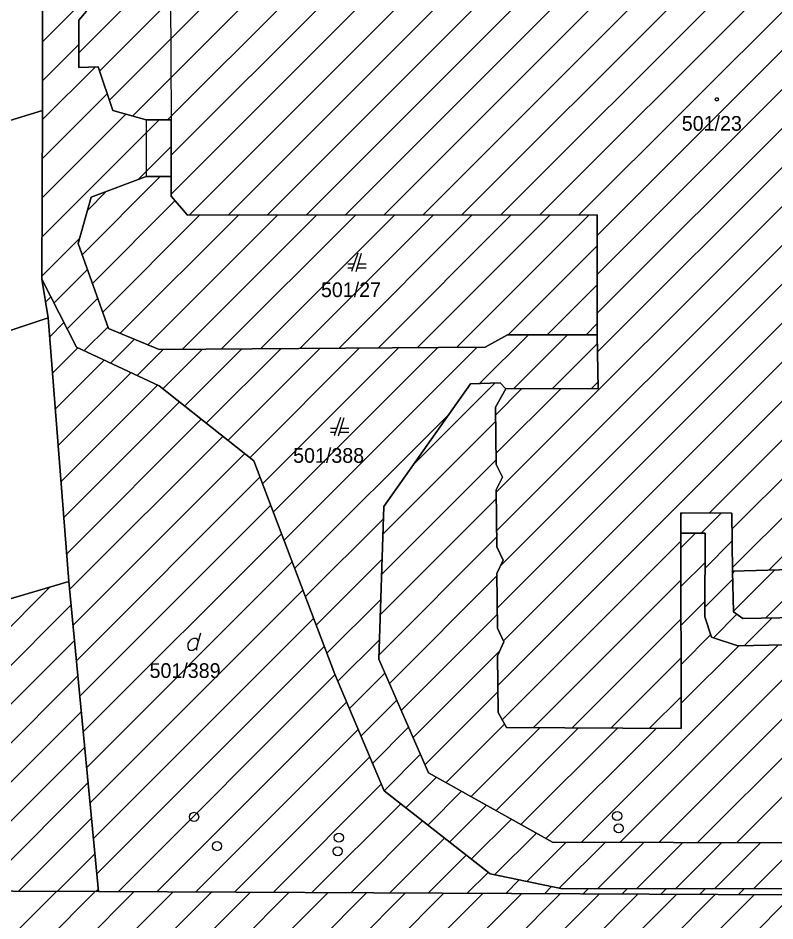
# Model space of a CAD drawing. Extents: x -264309 to -263505, y -1242443 to -1241763.
# Drawn here: x -264079.6 to -263997.1, y -1242199.4 to -1242101 of the extents above; entities that cross this region are included whole.
import ezdxf

# ---------------------------------------------------------------- set-up
doc = ezdxf.new("R2010")
doc.units = 0
for name, color, linetype in [('KFA_SO_40-3_SACHTY_POKLOPY', 7, 'Continuous'), ('KN_2019_08_16_KLADPAR', 7, 'Continuous'), ('KN_2019_08_16_ZAPPAR', 7, 'Continuous'), ('SRAFY_PARCELY', 7, 'Continuous')]:
    doc.layers.add(name, color=color, linetype=linetype)

msp = doc.modelspace()

# ---------------------------------------------------------------- linework, layer by layer
at = {"layer": 'KFA_SO_40-3_SACHTY_POKLOPY'}
for centre in [(-264014.309, -1242187.956), (-264060.398, -1242188.048), (-264014.146, -1242189.299), (-264044.631, -1242190.302), (-264057.903, -1242191.227), (-264044.758, -1242191.792)]:
    msp.add_circle(centre, 0.5, dxfattribs=at)
at = {"layer": 'KN_2019_08_16_KLADPAR'}
for p, q in [((-264042.56, -1242126.66), (-264043.26, -1242128.66)), ((-264042.76, -1242128.66), (-264042.16, -1242126.66)), ((-264042.98, -1242127.86), (-264043.66, -1242127.86)), ((-264043.66, -1242128.26), (-264043.12, -1242128.26)), ((-264042.64, -1242128.26), (-264041.66, -1242128.26)), ((-264041.66, -1242127.86), (-264042.52, -1242127.86)), ((-264044.45, -1242144.55), (-264045.15, -1242146.55)), ((-264044.65, -1242146.55), (-264044.05, -1242144.55)), ((-264044.87, -1242145.75), (-264045.55, -1242145.75)), ((-264045.55, -1242146.15), (-264045.01, -1242146.15)), ((-264044.53, -1242146.15), (-264043.55, -1242146.15)), ((-264043.55, -1242145.75), (-264044.41, -1242145.75)), ((-264059.92, -1242168.89), (-264059.65, -1242167.99))]:
    msp.add_line(p, q, dxfattribs=at)
for points in [[(-264246.81, -1242153.57), (-264207.96, -1242133.21), (-264176.83, -1242121.28), (-264120.91, -1242102.78), (-264081.08, -1242089.93), (-264076.9, -1242098.2), (-264076.93, -1242111.1), (-264102.41, -1242118.92), (-264128.45, -1242126.51), (-264158.28, -1242134.19), (-264188.56, -1242145.27), (-264215.11, -1242156.51), (-264222.8, -1242159.81), (-264237.43, -1242168.42)], [(-264003.37, -1242109.74), (-264003.28, -1242109.89), (-264003.37, -1242110.04), (-264003.55, -1242110.04), (-264003.64, -1242109.89), (-264003.55, -1242109.74)], [(-264076.93, -1242111.1), (-264076.98, -1242129.46), (-264076.3, -1242133.7), (-264095.55, -1242140.08), (-264157.05, -1242153.68), (-264195.05, -1242168.92), (-264211.96, -1242175.6), (-264215.03, -1242177.17), (-264227.71, -1242183.68), (-264237.43, -1242168.42), (-264222.8, -1242159.81), (-264215.11, -1242156.51), (-264188.56, -1242145.27), (-264158.28, -1242134.19), (-264128.45, -1242126.51), (-264102.41, -1242118.92)], [(-264016.47, -1242135.53), (-264026.27, -1242135.54), (-264028.68, -1242136.88), (-264064.2, -1242137.12), (-264069.71, -1242134.85), (-264073.04, -1242125.6), (-264071.61, -1242120.55), (-264065.61, -1242118.31), (-264062.88, -1242118.3), (-264062.88, -1242120.44), (-264061.11, -1242122.5), (-264016.48, -1242122.48)], [(-263988.88, -1242124.89), (-263983.88, -1242124.73), (-263977.77, -1242124.63), (-263973.88, -1242126.53), (-263972.33, -1242129.65), (-263972.09, -1242163.43), (-263972.93, -1242164.99), (-263974.51, -1242165.96), (-264000.63, -1242166.44), (-264001.62, -1242165.72), (-264001.73, -1242161.29), (-263988.91, -1242160.93)], [(-264070.8, -1242196.19), (-264074.04, -1242162.41), (-264076.3, -1242133.7), (-264076.98, -1242129.46), (-264073.21, -1242136.9), (-264064.2, -1242141.11), (-264053.9, -1242149.28), (-264045.08, -1242172.51), (-264039.7, -1242185.21), (-264028.16, -1242194.26), (-264020.26, -1242195.89), (-263967.07, -1242195.86), (-263959.05, -1242193.86), (-263950.83, -1242187.66), (-263949.38, -1242187.85), (-263949.41, -1242196.68), (-263950.84, -1242196.76)], [(-264195.05, -1242168.92), (-264157.05, -1242153.68), (-264095.55, -1242140.08), (-264076.3, -1242133.7), (-264074.04, -1242162.41), (-264177.6, -1242192.97)], [(-264212.29, -1242180.92), (-264215.03, -1242177.17), (-264211.96, -1242175.6), (-264195.05, -1242168.92), (-264177.6, -1242192.97), (-264074.04, -1242162.41), (-264070.8, -1242196.19), (-264098.84, -1242196.05), (-264099.36, -1242306.05), (-264115.27, -1242315.84), (-264137.78, -1242284.52)], [(-263950.84, -1242196.76), (-263951.29, -1242290.6), (-263951.37, -1242306.76), (-264045.86, -1242306.31), (-264099.36, -1242306.05), (-264098.84, -1242196.05), (-264070.8, -1242196.19)]]:
    msp.add_lwpolyline(points, close=True, dxfattribs=at)
for points in [[(-263967.07, -1242195.86), (-264020.26, -1242195.89), (-264028.16, -1242194.26), (-264039.7, -1242185.21), (-264045.08, -1242172.51), (-264053.9, -1242149.28), (-264064.2, -1242141.11), (-264073.21, -1242136.9), (-264076.98, -1242129.46), (-264076.93, -1242111.1), (-264076.9, -1242098.2)], [(-264072.11, -1242100.28), (-264072.96, -1242101.25), (-264072.96, -1242106.41), (-264070.85, -1242106.36), (-264069.25, -1242111.12), (-264065.62, -1242112.13), (-264062.89, -1242112.12), (-264062.88, -1242118.3), (-264065.61, -1242118.31), (-264071.61, -1242120.55), (-264073.04, -1242125.6), (-264069.71, -1242134.85), (-264064.2, -1242137.12), (-264028.68, -1242136.88), (-264026.27, -1242135.54), (-264016.47, -1242135.53), (-264016.38, -1242141.37), (-264026.42, -1242141.41), (-264027.07, -1242140.78), (-264030.29, -1242140.89), (-264039.73, -1242154.25), (-264040.29, -1242170.87), (-264034.85, -1242183.24), (-264021.34, -1242190.81), (-263968.63, -1242190.95)], [(-263988.91, -1242160.93), (-264001.73, -1242161.29), (-264001.8, -1242154.96), (-264007.36, -1242154.93), (-264007.37, -1242157.14), (-264007.34, -1242178.42), (-264026.37, -1242178.31), (-264027.29, -1242176.68), (-264027.34, -1242170.52), (-264026.65, -1242168.99), (-264027.36, -1242167.48), (-264027.41, -1242161.52), (-264026.72, -1242160.07), (-264027.43, -1242158.63), (-264027.48, -1242152.43), (-264026.79, -1242151.05), (-264027.5, -1242149.68), (-264027.55, -1242143.43), (-264026.42, -1242141.41), (-264016.38, -1242141.37), (-264016.47, -1242135.53), (-264016.48, -1242122.48), (-264061.11, -1242122.5), (-264062.88, -1242120.44), (-264062.88, -1242118.3), (-264062.89, -1242112.12), (-264065.62, -1242112.13), (-264069.25, -1242111.12), (-264070.85, -1242106.36), (-264072.96, -1242106.41), (-264072.96, -1242101.25), (-264072.11, -1242100.28)], [(-263968.63, -1242190.95), (-264021.34, -1242190.81), (-264034.85, -1242183.24), (-264040.29, -1242170.87), (-264039.73, -1242154.25), (-264030.29, -1242140.89), (-264027.07, -1242140.78), (-264026.42, -1242141.41), (-264027.55, -1242143.43), (-264027.5, -1242149.68), (-264026.79, -1242151.05), (-264027.48, -1242152.43), (-264027.43, -1242158.63), (-264026.72, -1242160.07), (-264027.41, -1242161.52), (-264027.36, -1242167.48), (-264026.65, -1242168.99), (-264027.34, -1242170.52), (-264027.29, -1242176.68), (-264026.37, -1242178.31), (-264007.34, -1242178.42), (-264007.37, -1242157.14), (-264004.73, -1242157.15), (-264004.75, -1242166.25), (-264004.02, -1242168.46), (-264001.16, -1242169.4), (-263955.56, -1242168.43)], [(-263955.56, -1242168.43), (-264001.16, -1242169.4), (-264004.02, -1242168.46), (-264004.75, -1242166.25), (-264004.73, -1242157.15), (-264007.37, -1242157.14), (-264007.36, -1242154.93), (-264001.8, -1242154.96), (-264001.73, -1242161.29), (-264001.62, -1242165.72), (-264000.63, -1242166.44), (-263974.51, -1242165.96)], [(-264060.1, -1242169.88), (-264060.1, -1242169.61), (-264059.92, -1242168.89), (-264060.01, -1242168.71), (-264060.19, -1242168.62), (-264060.46, -1242168.62), (-264060.73, -1242168.71), (-264060.91, -1242168.89), (-264061.09, -1242169.16), (-264061.09, -1242169.52), (-264061, -1242169.79), (-264060.82, -1242169.88), (-264060.55, -1242169.88), (-264060.37, -1242169.79), (-264060.1, -1242169.61)]]:
    msp.add_lwpolyline(points, dxfattribs=at)
at = {"layer": 'KN_2019_08_16_ZAPPAR'}
for p, q in [((-264063.02, -1242088.27), (-264062.89, -1242112.12)), ((-264065.62, -1242112.13), (-264065.61, -1242118.31))]:
    msp.add_line(p, q, dxfattribs=at)
at = {"layer": 'SRAFY_PARCELY'}
for p, q in [((-264072.96, -1242104.826), (-264045.841, -1242077.707)), ((-264070.699, -1242106.808), (-264041.592, -1242077.7)), ((-264069.632, -1242109.983), (-264037.342, -1242077.694)), ((-264067.119, -1242111.713), (-264033.093, -1242077.687)), ((-264063.285, -1242112.121), (-264028.844, -1242077.681)), ((-264062.884, -1242115.963), (-264024.595, -1242077.674)), ((-264062.88, -1242120.202), (-264020.346, -1242077.668)), ((-264060.935, -1242122.5), (-264016.097, -1242077.661)), ((-264056.691, -1242122.498), (-264011.848, -1242077.655)), ((-264052.446, -1242122.496), (-264007.599, -1242077.649)), ((-264048.202, -1242122.494), (-264003.35, -1242077.642)), ((-264043.957, -1242122.492), (-264001.663, -1242080.198)), ((-264039.713, -1242122.49), (-263997.265, -1242080.043)), ((-264035.468, -1242122.489), (-263993.026, -1242080.046)), ((-264031.224, -1242122.487), (-263988.846, -1242080.109)), ((-264026.979, -1242122.485), (-263984.667, -1242080.173)), ((-264022.735, -1242122.483), (-263981.762, -1242081.51)), ((-264018.49, -1242122.481), (-263977.519, -1242081.51)), ((-264016.478, -1242124.712), (-263975.759, -1242083.993)), ((-264016.475, -1242128.951), (-263975.725, -1242088.201)), ((-264016.472, -1242133.191), (-263975.69, -1242092.409)), ((-264016.441, -1242137.403), (-263972.66, -1242093.621)), ((-264027.478, -1242152.682), (-263970.237, -1242095.441)), ((-264076.913, -1242103.615), (-264072.792, -1242099.494)), ((-264027.444, -1242156.891), (-263970.23, -1242099.677)), ((-264076.922, -1242107.867), (-264072.96, -1242103.905)), ((-264076.933, -1242112.12), (-264071.18, -1242106.368)), ((-264076.944, -1242116.374), (-264069.864, -1242109.294)), ((-264027.028, -1242160.717), (-263975.58, -1242109.269)), ((-264076.956, -1242120.629), (-264067.84, -1242111.512)), ((-264076.968, -1242124.883), (-264064.21, -1242112.125)), ((-264066.475, -1242118.633), (-264062.885, -1242115.043)), ((-264072.603, -1242126.815), (-264064.092, -1242118.304)), ((-264072.017, -1242121.987), (-264069.967, -1242119.936)), ((-264071.48, -1242129.935), (-264062.466, -1242120.921)), ((-264070.356, -1242133.054), (-264059.802, -1242122.499)), ((-264068.435, -1242135.375), (-264055.557, -1242122.498)), ((-264065.43, -1242136.613), (-264051.313, -1242122.496)), ((-264061.677, -1242137.103), (-264047.068, -1242122.494)), ((-264057.406, -1242137.074), (-264042.823, -1242122.492)), ((-264053.134, -1242137.045), (-264038.579, -1242122.49)), ((-264048.863, -1242137.016), (-264034.334, -1242122.488)), ((-264044.591, -1242136.988), (-264030.09, -1242122.486)), ((-264040.32, -1242136.959), (-264025.845, -1242122.484)), ((-264036.048, -1242136.93), (-264021.601, -1242122.482)), ((-264031.777, -1242136.901), (-264017.356, -1242122.48)), ((-264076.979, -1242129.137), (-264072.881, -1242125.039)), ((-264026.173, -1242135.54), (-264016.477, -1242125.844)), ((-264027.378, -1242165.31), (-263988.882, -1242126.814)), ((-264075.661, -1242132.062), (-264072.023, -1242128.424)), ((-264021.926, -1242135.536), (-264016.474, -1242130.084)), ((-264076.577, -1242131.975), (-264075.999, -1242131.397)), ((-264026.703, -1242168.877), (-263988.885, -1242131.06)), ((-264074.235, -1242134.878), (-264070.9, -1242131.544)), ((-264076.136, -1242135.777), (-264074.572, -1242134.213)), ((-264017.679, -1242135.531), (-264016.471, -1242134.323)), ((-264072.395, -1242137.281), (-264069.777, -1242134.663)), ((-264027.314, -1242173.731), (-263988.889, -1242135.306)), ((-264069.503, -1242138.632), (-264066.885, -1242136.014)), ((-264029.301, -1242140.856), (-264023.983, -1242135.538)), ((-264025.609, -1242141.407), (-264019.736, -1242135.533)), ((-264075.827, -1242139.711), (-264073.078, -1242136.962)), ((-264066.612, -1242139.983), (-264063.746, -1242137.117)), ((-264063.808, -1242141.421), (-264059.474, -1242137.088)), ((-264061.442, -1242143.298), (-264055.203, -1242137.059)), ((-264059.076, -1242145.175), (-264050.931, -1242137.03)), ((-264056.71, -1242147.051), (-264046.66, -1242137.001)), ((-264054.344, -1242148.928), (-264042.388, -1242136.973)), ((-264052.951, -1242151.778), (-264038.117, -1242136.944)), ((-264051.784, -1242154.853), (-264033.845, -1242136.915)), ((-264050.616, -1242157.929), (-264029.574, -1242136.886)), ((-264021.35, -1242141.39), (-264016.455, -1242136.495)), ((-264075.517, -1242143.644), (-264070.186, -1242138.313)), ((-264075.208, -1242147.577), (-264067.295, -1242139.664)), ((-264004.287, -1242154.947), (-263988.892, -1242139.552)), ((-264074.898, -1242151.51), (-264064.403, -1242141.015)), ((-264036.5, -1242149.678), (-264027.62, -1242140.799)), ((-264017.09, -1242141.373), (-264016.391, -1242140.674)), ((-264027.543, -1242144.262), (-264024.684, -1242141.403)), ((-264027.51, -1242148.471), (-264020.425, -1242141.386)), ((-264074.588, -1242155.443), (-264062, -1242142.855)), ((-264049.449, -1242161.004), (-264032.589, -1242144.144)), ((-264001.781, -1242156.683), (-263988.896, -1242143.798)), ((-264074.279, -1242159.376), (-264059.635, -1242144.731)), ((-264039.831, -1242157.252), (-264027.538, -1242144.959)), ((-264073.955, -1242163.295), (-264057.269, -1242146.608)), ((-264001.735, -1242160.88), (-263988.899, -1242148.044)), ((-264073.584, -1242167.166), (-264054.903, -1242148.485)), ((-264039.979, -1242161.643), (-264027.504, -1242149.168)), ((-264073.213, -1242171.037), (-264053.227, -1242151.052)), ((-263997.792, -1242161.179), (-263988.903, -1242152.291)), ((-264040.127, -1242166.034), (-264027.472, -1242153.379)), ((-264072.841, -1242174.909), (-264052.06, -1242154.127)), ((-264007.361, -1242155.096), (-264007.196, -1242154.931)), ((-264005.17, -1242157.148), (-264002.976, -1242154.954)), ((-264048.281, -1242164.079), (-264039.775, -1242155.572)), ((-264072.47, -1242178.78), (-264050.892, -1242157.202)), ((-264040.275, -1242170.424), (-264027.438, -1242157.588)), ((-264007.368, -1242158.73), (-264005.784, -1242157.146)), ((-264026.832, -1242177.492), (-264007.369, -1242158.029)), ((-264004.738, -1242160.959), (-264001.767, -1242157.987)), ((-264072.099, -1242182.651), (-264049.725, -1242160.277)), ((-264047.114, -1242167.154), (-264039.922, -1242159.963)), ((-264007.362, -1242162.967), (-264004.737, -1242160.342)), ((-264039.126, -1242173.518), (-264027.408, -1242161.799)), ((-264001.725, -1242161.49), (-264001.519, -1242161.284)), ((-264001.622, -1242165.63), (-263997.154, -1242161.161)), ((-263998.144, -1242166.394), (-263992.789, -1242161.039)), ((-264023.425, -1242178.327), (-264007.363, -1242162.265)), ((-264004.748, -1242165.211), (-264001.708, -1242162.171)), ((-264162.807, -1242249.722), (-264076.104, -1242163.019)), ((-264071.727, -1242186.523), (-264048.557, -1242163.352)), ((-264045.946, -1242170.229), (-264040.07, -1242164.353)), ((-264007.356, -1242167.203), (-264004.746, -1242164.594)), ((-264161.032, -1242252.19), (-264073.796, -1242164.954)), ((-264071.356, -1242190.394), (-264047.389, -1242166.427)), ((-264037.83, -1242176.464), (-264027.372, -1242166.007)), ((-264019.206, -1242178.351), (-264007.357, -1242166.502)), ((-264003.82, -1242168.526), (-264001.269, -1242165.975)), ((-264000.436, -1242169.385), (-263997.433, -1242166.381)), ((-264044.754, -1242173.279), (-264040.218, -1242168.744)), ((-264007.35, -1242171.44), (-264004.107, -1242168.197)), ((-264159.257, -1242254.658), (-264073.425, -1242168.825)), ((-264070.985, -1242194.265), (-264046.222, -1242169.503)), ((-264018.243, -1242190.818), (-263996.73, -1242169.306)), ((-264014.011, -1242190.829), (-263992.395, -1242169.214)), ((-264009.78, -1242190.841), (-263988.06, -1242169.121)), ((-264007.344, -1242175.677), (-264001.065, -1242169.398)), ((-264005.548, -1242190.852), (-263983.726, -1242169.029)), ((-264001.317, -1242190.863), (-263979.391, -1242168.937)), ((-264036.534, -1242179.411), (-264027.091, -1242169.968)), ((-264014.988, -1242178.376), (-264007.351, -1242170.739)), ((-264096.419, -1242196.062), (-264073.053, -1242172.696)), ((-264068.677, -1242196.2), (-264045.052, -1242172.576)), ((-264043.492, -1242176.26), (-264039.622, -1242172.39)), ((-264035.238, -1242182.358), (-264027.308, -1242174.428)), ((-264064.454, -1242196.22), (-264043.79, -1242175.556)), ((-264042.229, -1242179.24), (-264038.326, -1242175.336)), ((-264010.77, -1242178.4), (-264007.345, -1242174.975)), ((-264092.198, -1242196.083), (-264072.682, -1242176.568)), ((-264060.232, -1242196.24), (-264042.527, -1242178.536)), ((-264040.967, -1242182.22), (-264037.03, -1242178.283)), ((-264032.945, -1242184.307), (-264026.578, -1242177.941)), ((-264030.226, -1242185.831), (-264022.726, -1242178.331)), ((-264027.507, -1242187.355), (-264018.508, -1242178.355)), ((-264024.788, -1242188.878), (-264014.29, -1242178.38)), ((-264022.069, -1242190.402), (-264010.071, -1242178.404)), ((-264087.976, -1242196.104), (-264072.311, -1242180.439)), ((-264056.009, -1242196.26), (-264041.265, -1242181.516)), ((-264039.704, -1242185.2), (-264035.734, -1242181.23)), ((-264083.755, -1242196.125), (-264071.939, -1242184.31)), ((-264051.787, -1242196.28), (-264040.002, -1242184.496)), ((-264037.33, -1242187.069), (-264033.986, -1242183.724)), ((-264034.952, -1242188.933), (-264031.267, -1242185.248)), ((-264047.564, -1242196.3), (-264037.892, -1242186.628)), ((-264032.574, -1242190.798), (-264028.548, -1242186.771)), ((-264079.533, -1242196.146), (-264071.568, -1242188.181)), ((-264030.196, -1242192.663), (-264025.828, -1242188.295)), ((-264043.341, -1242196.32), (-264035.514, -1242188.493)), ((-264039.119, -1242196.341), (-264033.136, -1242190.358)), ((-264027.655, -1242194.364), (-264023.109, -1242189.819)), ((-264024.138, -1242195.09), (-264019.862, -1242190.814)), ((-264020.621, -1242195.816), (-264015.631, -1242190.825)), ((-264016.451, -1242195.888), (-264011.399, -1242190.836)), ((-264012.206, -1242195.885), (-264007.168, -1242190.848)), ((-264007.961, -1242195.883), (-264002.936, -1242190.859)), ((-264003.716, -1242195.881), (-263998.705, -1242190.87)), ((-263999.471, -1242195.878), (-263994.474, -1242190.881)), ((-264075.311, -1242196.167), (-264071.197, -1242192.053)), ((-264034.896, -1242196.361), (-264030.758, -1242192.222)), ((-264030.674, -1242196.381), (-264028.38, -1242194.087)), ((-264026.451, -1242196.401), (-264024.969, -1242194.918)), ((-264099.113, -1242253.821), (-264041.621, -1242196.329)), ((-264099.093, -1242249.558), (-264045.843, -1242196.309)), ((-264099.073, -1242245.296), (-264050.066, -1242196.289)), ((-264099.053, -1242241.033), (-264054.288, -1242196.268)), ((-264099.032, -1242236.77), (-264058.511, -1242196.248)), ((-264099.012, -1242232.507), (-264062.733, -1242196.228)), ((-264098.992, -1242228.244), (-264066.956, -1242196.208)), ((-264098.972, -1242223.982), (-264071.179, -1242196.188)), ((-264098.952, -1242219.719), (-264075.4, -1242196.167)), ((-264071.09, -1242196.189), (-264070.825, -1242195.924)), ((-264022.228, -1242196.421), (-264021.452, -1242195.644)), ((-264018.006, -1242196.441), (-264017.453, -1242195.888)), ((-264013.783, -1242196.461), (-264013.208, -1242195.886)), ((-264009.561, -1242196.481), (-264008.963, -1242195.884)), ((-264005.338, -1242196.501), (-264004.718, -1242195.881)), ((-264001.116, -1242196.521), (-264000.473, -1242195.879)), ((-264099.335, -1242300.712), (-263995.172, -1242196.549)), ((-264099.315, -1242296.449), (-263999.395, -1242196.529)), ((-264099.294, -1242292.186), (-264003.617, -1242196.509)), ((-264099.274, -1242287.924), (-264007.84, -1242196.489)), ((-264099.254, -1242283.661), (-264012.063, -1242196.469)), ((-264099.234, -1242279.398), (-264016.285, -1242196.449)), ((-264099.214, -1242275.135), (-264020.508, -1242196.429)), ((-264099.194, -1242270.872), (-264024.73, -1242196.409)), ((-264099.174, -1242266.61), (-264028.953, -1242196.389)), ((-264099.153, -1242262.347), (-264033.175, -1242196.369)), ((-264099.133, -1242258.084), (-264037.398, -1242196.349))]:
    msp.add_line(p, q, dxfattribs=at)

# ---------------------------------------------------------------- texts
at = {"layer": 'KN_2019_08_16_KLADPAR'}
for s, p in [('501/23', (-264007.269, -1242113.31)), ('501/27', (-264046.579, -1242131.43)), ('501/388', (-264049.611, -1242149.48)), ('501/389', (-264065.251, -1242172.91))]:
    msp.add_text(s, height=1.6, dxfattribs=at).set_placement(p)

doc.saveas('drawing.dxf')
